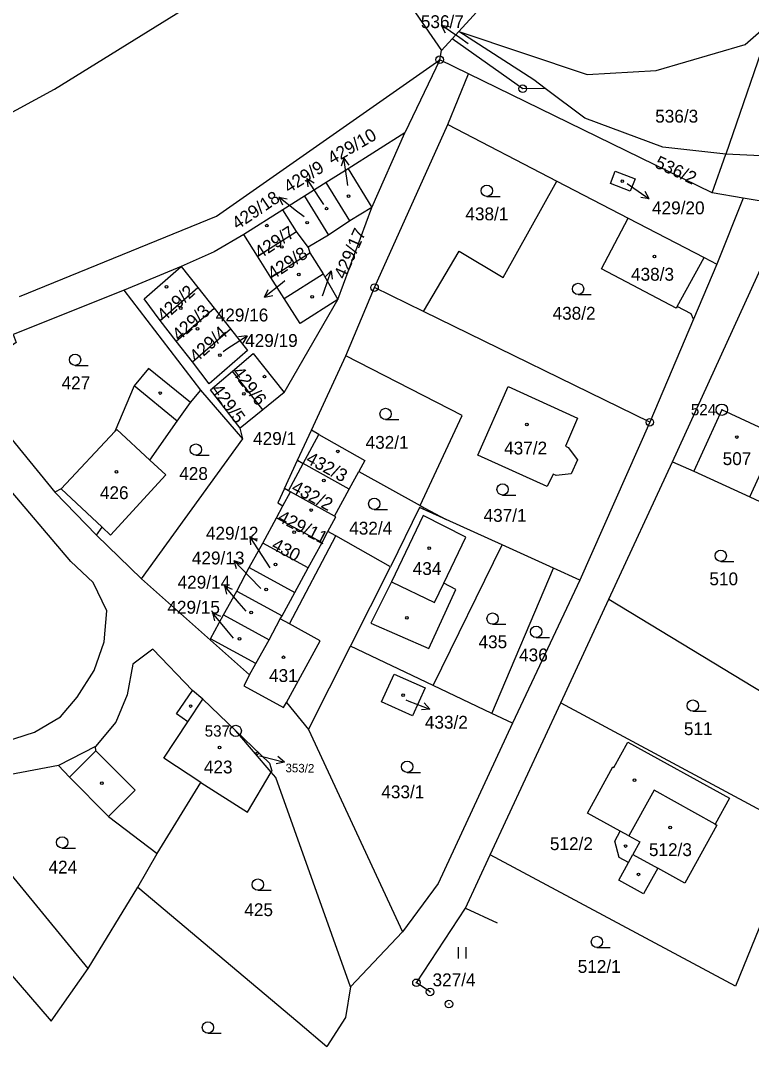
# Model space of a CAD drawing. Extents: x -776701 to -776081, y -974398 to -973771.
# Drawn here: x -776380.3 to -776283.6, y -974398.3 to -974262.5 of the extents above; entities that cross this region are included whole.
import ezdxf

# ---------------------------------------------------------------- set-up
doc = ezdxf.new("R2010")
doc.units = 0
for name, color, linetype in [('Hranice parcel', 7, 'Continuous'), ('Parcelní čísla', 7, 'Continuous'), ('Pop  PČ popisy', 7, 'Continuous'), ('Poz předměty', 7, 'Continuous'), ('Vnitřní kresba', 7, 'Continuous'), ('Značky bodu BP', 7, 'Continuous'), ('Značky budov', 7, 'Continuous'), ('Značky kultur', 7, 'Continuous')]:
    doc.layers.add(name, color=color, linetype=linetype)

msp = doc.modelspace()

# ---------------------------------------------------------------- linework, layer by layer
at = {"layer": 'Hranice parcel'}
for p, q in [((-776280.95, -974262.62), (-776287.02, -974280.17)), ((-776323.22, -974264.9), (-776322.34, -974263.94)), ((-776288.8, -974285.31), (-776287.02, -974280.17)), ((-776279.48, -974280.55), (-776287.02, -974280.17)), ((-776336.99, -974282.11), (-776339.88, -974283.93)), ((-776339.88, -974283.93), (-776342.75, -974285.75)), ((-776336.75, -974289), (-776339.88, -974283.93)), ((-776309.36, -974283.76), (-776299.93, -974288.65)), ((-776342.75, -974285.75), (-776345.62, -974287.57)), ((-776342.75, -974285.75), (-776339.6, -974290.9)), ((-776284.72, -974286.01), (-776288.8, -974285.31)), ((-776284.72, -974286.01), (-776288.19, -974294.73)), ((-776275.72, -974287.55), (-776284.72, -974286.01)), ((-776345.62, -974287.57), (-776350.78, -974290.83)), ((-776343.81, -974290.44), (-776345.62, -974287.57)), ((-776336.75, -974289), (-776339.6, -974290.9)), ((-776299.93, -974288.65), (-776289.9, -974293.84)), ((-776348.97, -974293.7), (-776343.81, -974290.44)), ((-776342.3, -974292.5), (-776343.81, -974290.44)), ((-776348.97, -974293.7), (-776350.78, -974290.83)), ((-776339.6, -974290.9), (-776342.3, -974292.5)), ((-776347.2, -974296.49), (-776342.04, -974293.23)), ((-776342.3, -974292.5), (-776342.04, -974293.23)), ((-776342.04, -974293.23), (-776340.28, -974296.02)), ((-776347.2, -974296.49), (-776348.97, -974293.7)), ((-776289.9, -974293.84), (-776288.19, -974294.73)), ((-776288.19, -974294.73), (-776291.28, -974302.01)), ((-776345.44, -974299.28), (-776347.2, -974296.49)), ((-776345.44, -974299.28), (-776340.28, -974296.02)), ((-776366.62, -974298.19), (-776381.33, -974304.06)), ((-776356.49, -974311.44), (-776366.62, -974298.19)), ((-776361.87, -974302.2), (-776356.9, -974297.82)), ((-776356.9, -974297.82), (-776354.73, -974300.57)), ((-776337.3, -974306.86), (-776333.5, -974297.85)), ((-776327.02, -974301.02), (-776333.5, -974297.85)), ((-776359.74, -974304.94), (-776354.73, -974300.57)), ((-776354.73, -974300.57), (-776352.57, -974303.31)), ((-776297.07, -974315.67), (-776327.02, -974301.02)), ((-776359.74, -974304.94), (-776361.87, -974302.2)), ((-776291.28, -974302.01), (-776297.07, -974315.67)), ((-776357.6, -974307.68), (-776352.57, -974303.31)), ((-776357.6, -974307.68), (-776359.74, -974304.94)), ((-776348.28, -974314.03), (-776352.31, -974308.92)), ((-776357.83, -974313.04), (-776356.49, -974311.44)), ((-776297.07, -974315.67), (-776306.32, -974336.58)), ((-776343.69, -974320.7), (-776342.94, -974321.12)), ((-776336.85, -974324.51), (-776342.94, -974321.12)), ((-776302.5, -974339.06), (-776294.07, -974320.91)), ((-776294.07, -974320.91), (-776291.26, -974322.16)), ((-776368.42, -974330.59), (-776361.1, -974322.64)), ((-776336.85, -974324.51), (-776335.58, -974322.18)), ((-776335.58, -974322.18), (-776327.45, -974326.69)), ((-776291.26, -974322.16), (-776283.82, -974325.55)), ((-776375.79, -974324.92), (-776370.28, -974330.61)), ((-776338.81, -974328.09), (-776344.62, -974324.87)), ((-776338.81, -974328.09), (-776336.85, -974324.51)), ((-776283.82, -974325.55), (-776270.54, -974331.71)), ((-776348.3, -974331.65), (-776346.48, -974328.3)), ((-776346.48, -974328.3), (-776340.45, -974331.57)), ((-776316.6, -974331.91), (-776324.04, -974328.54)), ((-776370.28, -974330.61), (-776364.35, -974336.4)), ((-776340.45, -974331.57), (-776339.66, -974330.11)), ((-776350.07, -974334.91), (-776348.3, -974331.65)), ((-776342.26, -974334.92), (-776348.3, -974331.65)), ((-776342.26, -974334.92), (-776340.45, -974331.57)), ((-776325.72, -974350.5), (-776316.6, -974331.91)), ((-776309.81, -974334.99), (-776316.6, -974331.91)), ((-776351.74, -974338), (-776350.07, -974334.91)), ((-776350.07, -974334.91), (-776344.03, -974338.19)), ((-776344.03, -974338.19), (-776342.26, -974334.92)), ((-776336.7, -974345.3), (-776331.37, -974334.81)), ((-776317.97, -974354.21), (-776309.81, -974334.99)), ((-776306.32, -974336.58), (-776309.81, -974334.99)), ((-776364.35, -974336.4), (-776350.04, -974349.11)), ((-776306.32, -974336.58), (-776315.26, -974355.5)), ((-776353.47, -974341.17), (-776351.74, -974338)), ((-776351.74, -974338), (-776345.71, -974341.27)), ((-776345.71, -974341.27), (-776344.03, -974338.19)), ((-776308.85, -974352.8), (-776302.5, -974339.06)), ((-776302.5, -974339.06), (-776278.24, -974353.79)), ((-776353.47, -974341.17), (-776347.43, -974344.44)), ((-776349.2, -974347.58), (-776347.43, -974344.44)), ((-776342.23, -974356.34), (-776336.7, -974345.3)), ((-776325.72, -974350.5), (-776336.7, -974345.3)), ((-776350.04, -974349.11), (-776349.2, -974347.58)), ((-776317.97, -974354.21), (-776325.72, -974350.5)), ((-776318.19, -974372.93), (-776308.85, -974352.8)), ((-776308.85, -974352.8), (-776277.4, -974369.72)), ((-776315.26, -974355.5), (-776317.97, -974354.21)), ((-776347.17, -974361.99), (-776351.87, -974356.52)), ((-776342.23, -974356.34), (-776329.79, -974383.11)), ((-776362.24, -974372.74), (-776356.48, -974363.36)), ((-776371.4, -974387.94), (-776390.84, -974364.25)), ((-776400.26, -974367.17), (-776376.3, -974394.94)), ((-776277.4, -974369.72), (-776285.72, -974390.31)), ((-776364.8, -974377.2), (-776362.24, -974372.74)), ((-776321.45, -974379.97), (-776318.19, -974372.93)), ((-776285.72, -974390.31), (-776318.19, -974372.93)), ((-776371.4, -974387.94), (-776364.8, -974377.2)), ((-776364.8, -974377.2), (-776343.63, -974395.04)), ((-776327.95, -974389.85), (-776321.45, -974379.97)), ((-776321.45, -974379.97), (-776317.26, -974381.91)), ((-776329.79, -974383.11), (-776336.7, -974390.37)), ((-776376.3, -974394.94), (-776371.4, -974387.94)), ((-776326.15, -974391.06), (-776327.95, -974389.85)), ((-776343.63, -974395.04), (-776339.79, -974398.28))]:
    msp.add_line(p, q, dxfattribs=at)
for points in [[(-776322.34, -974263.94), (-776316.64, -974257.67), (-776307.88, -974259.63), (-776300.82, -974259.07), (-776293.46, -974256.12), (-776281.91, -974242.23)], [(-776322.34, -974263.94), (-776305.38, -974269.65), (-776296.22, -974269.13), (-776284.45, -974265.69), (-776280.95, -974262.62)], [(-776310.94, -974271.48), (-776312.43, -974270.36), (-776322.34, -974263.94)], [(-776324.88, -974267.68), (-776324.63, -974266.46), (-776323.22, -974264.9)], [(-776310.94, -974271.48), (-776313.89, -974271.52), (-776323.22, -974264.9)], [(-776380.5, -974299.02), (-776354.39, -974288.37), (-776324.88, -974267.68)], [(-776324.88, -974267.68), (-776329.47, -974277.36), (-776336.99, -974282.11)], [(-776288.8, -974285.31), (-776321.08, -974269.54), (-776324.88, -974267.68)], [(-776287.02, -974280.17), (-776295.33, -974279.25), (-776305.65, -974275.44), (-776310.94, -974271.48)], [(-776333.5, -974297.85), (-776323.82, -974276.26), (-776309.36, -974283.76)], [(-776336.99, -974282.11), (-776333.86, -974287.23), (-776336.75, -974289)], [(-776301.64, -974282.42), (-776299, -974283.46), (-776299.66, -974285.07), (-776302.28, -974284.07), (-776301.64, -974282.42)], [(-776327.02, -974301.02), (-776322.3, -974293.03), (-776316.46, -974296.49), (-776309.36, -974283.76)], [(-776291.28, -974302.01), (-776291.59, -974301.3), (-776293.47, -974300.35), (-776293.59, -974300.57), (-776303.47, -974295.37), (-776299.93, -974288.65)], [(-776350.78, -974290.83), (-776354.72, -974293.13), (-776359.09, -974295.04), (-776366.62, -974298.19)], [(-776294.07, -974320.91), (-776281.24, -974292.8), (-776280.11, -974290.91)], [(-776361.87, -974302.2), (-776364, -974299.35), (-776359.09, -974295.04), (-776356.9, -974297.82)], [(-776340.28, -974296.02), (-776338.37, -974299.42), (-776343.35, -974302.58), (-776345.44, -974299.28)], [(-776381.33, -974304.06), (-776380.93, -974305.13), (-776384.89, -974307.87), (-776385.42, -974309.83), (-776385.09, -974312.64), (-776383.44, -974315.62), (-776375.79, -974324.92)], [(-776352.57, -974303.31), (-776350.3, -974306.18), (-776355.38, -974310.58), (-776357.6, -974307.68)], [(-776352.31, -974308.92), (-776349.57, -974306.58), (-776345.45, -974311.72), (-776348.28, -974314.03)], [(-776343.69, -974320.7), (-776341.86, -974316.73), (-776337.3, -974306.86)], [(-776327.45, -974326.69), (-776321.89, -974314.77), (-776337.3, -974306.86)], [(-776383.87, -974358.38), (-776378.5, -974356.68), (-776375.04, -974354.64), (-776372.83, -974352.03), (-776370.62, -974348.5), (-776369.27, -974344.71), (-776368.91, -974340.64), (-776370.74, -974336.88), (-776373.7, -974334.1), (-776391.97, -974312.58), (-776393.45, -974309.32)], [(-776357.83, -974313.04), (-776363.4, -974308.53), (-776365.3, -974310.86), (-776367.86, -974316.89), (-776374.96, -974324.46), (-776375.79, -974324.92)], [(-776348.28, -974314.03), (-776351.28, -974316.46), (-776355.2, -974311.38), (-776352.31, -974308.92)], [(-776364.35, -974336.4), (-776350.91, -974317.88), (-776356.49, -974311.44)], [(-776309.88, -974322.53), (-776310.64, -974324.19), (-776319.84, -974320.01), (-776315.83, -974310.94), (-776306.65, -974315.14), (-776308.25, -974318.84), (-776307.86, -974319.01), (-776306.66, -974320.63), (-776307.5, -974322.47), (-776309.47, -974322.71), (-776309.88, -974322.53)], [(-776361.1, -974322.64), (-776363.24, -974320.67), (-776359.6, -974315.52), (-776357.83, -974313.04)], [(-776283.82, -974325.55), (-776280.13, -974317.46), (-776287.54, -974314), (-776291.26, -974322.16)], [(-776342.94, -974321.12), (-776340.87, -974317.29), (-776334.78, -974320.71), (-776335.58, -974322.18)], [(-776344.62, -974324.87), (-776344.9, -974324.72), (-776345.42, -974324.44), (-776343.69, -974320.7)], [(-776346.48, -974328.3), (-776345.63, -974326.73), (-776344.62, -974324.87)], [(-776324.04, -974328.54), (-776327.56, -974326.94), (-776331.37, -974334.81)], [(-776327.45, -974326.69), (-776326.94, -974326.97), (-776324.04, -974328.54)], [(-776339.66, -974330.11), (-776338.61, -974328.2), (-776338.81, -974328.09)], [(-776370.28, -974330.61), (-776369.53, -974329.55), (-776368.42, -974330.59)], [(-776331.37, -974334.81), (-776338.64, -974330.69), (-776339.66, -974330.11)], [(-776349.2, -974347.58), (-776355.19, -974344.34), (-776353.47, -974341.17)], [(-776347.43, -974344.44), (-776345.98, -974341.7), (-776345.71, -974341.27)], [(-776351.87, -974356.52), (-776356.2, -974352.3), (-776357.6, -974351.15), (-776362.85, -974345.69), (-776365.48, -974347.69), (-776366.22, -974351.74), (-776367.74, -974355.38), (-776370.41, -974358.58), (-776375.3, -974361.1)], [(-776350.04, -974349.11), (-776350.79, -974350.53), (-776345.53, -974353.4), (-776345.17, -974352.74), (-776342.23, -974356.34)], [(-776326.82, -974350.83), (-776328.48, -974354.52), (-776332.58, -974352.68), (-776330.92, -974348.99), (-776326.82, -974350.83)], [(-776315.26, -974355.5), (-776325.06, -974376.72), (-776329.79, -974383.11)], [(-776351.87, -974356.52), (-776347.38, -974360.77), (-776347.07, -974361.81), (-776347.17, -974361.99)], [(-776296.02, -974374.69), (-776297.89, -974378.09), (-776301.18, -974376.28), (-776299.9, -974373.95), (-776301.11, -974373.29), (-776301.72, -974371.1), (-776300.99, -974369.78), (-776305.33, -974367.39), (-776301.97, -974361.28), (-776301.82, -974361.36), (-776299.98, -974358.02), (-776286.51, -974365.42), (-776288.41, -974368.87)], [(-776375.3, -974361.1), (-776385.85, -974363.08), (-776390.84, -974364.25)], [(-776375.3, -974361.1), (-776373.87, -974362.65), (-776368.69, -974367.84), (-776362.24, -974372.74)], [(-776356.48, -974363.36), (-776350.29, -974367.25), (-776347.17, -974361.99)], [(-776336.7, -974390.37), (-776346.56, -974362.7), (-776347.17, -974361.99)], [(-776288.41, -974368.87), (-776288.19, -974368.99), (-776292.46, -974376.67), (-776296.02, -974374.69)], [(-776336.7, -974390.37), (-776337.32, -974394.45), (-776339.79, -974398.28)]]:
    msp.add_lwpolyline(points, dxfattribs=at)
at = {"layer": 'Pop  PČ popisy'}
for p, q in [((-776322.21, -974264.81), (-776324.7, -974263.13)), ((-776324.7, -974263.13), (-776323.59, -974263.28)), ((-776324.7, -974263.13), (-776324.15, -974264.11)), ((-776321.11, -974265.57), (-776322.21, -974264.81)), ((-776337.55, -974280.7), (-776337.9, -974281.76)), ((-776337.13, -974283.67), (-776337.55, -974280.7)), ((-776337.55, -974280.7), (-776336.91, -974281.62)), ((-776340.81, -974285.91), (-776342.44, -974283.39)), ((-776342.44, -974283.39), (-776341.48, -974283.96)), ((-776342.44, -974283.39), (-776342.32, -974284.51)), ((-776337.04, -974284.31), (-776337.13, -974283.67)), ((-776300.06, -974284.08), (-776299.63, -974284.37)), ((-776299.63, -974284.37), (-776297.17, -974286.09)), ((-776297.17, -974286.09), (-776297.7, -974285.11)), ((-776343.81, -974287.72), (-776346.18, -974285.87)), ((-776346.18, -974285.87), (-776345.08, -974286.09)), ((-776346.18, -974285.87), (-776345.69, -974286.88)), ((-776340.19, -974286.86), (-776340.81, -974285.91)), ((-776297.17, -974286.09), (-776298.28, -974285.93)), ((-776342.82, -974288.48), (-776343.81, -974287.72)), ((-776340.21, -974298.47), (-776339.23, -974295.63)), ((-776339.23, -974295.63), (-776340.03, -974296.42)), ((-776339.23, -974295.63), (-776339.09, -974296.74)), ((-776345.71, -974297.24), (-776348.04, -974299.13)), ((-776345.35, -974296.95), (-776345.71, -974297.24)), ((-776348.04, -974299.13), (-776347.58, -974298.11)), ((-776340.37, -974298.93), (-776340.21, -974298.47)), ((-776348.04, -974299.13), (-776346.95, -974298.89)), ((-776352.89, -974305.87), (-776350.37, -974304.24)), ((-776350.37, -974304.24), (-776351.49, -974304.36)), ((-776350.37, -974304.24), (-776350.94, -974305.2)), ((-776353.54, -974306.3), (-776352.89, -974305.87)), ((-776348.38, -974333.29), (-776350.01, -974330.77)), ((-776350.01, -974330.77), (-776349.05, -974331.34)), ((-776350.01, -974330.77), (-776349.89, -974331.89)), ((-776350.04, -974336.11), (-776352.12, -974333.95)), ((-776352.12, -974333.95), (-776351.07, -974334.32)), ((-776352.12, -974333.95), (-776351.79, -974335.02)), ((-776347.32, -974334.95), (-776348.38, -974333.29)), ((-776348.53, -974337.67), (-776350.04, -974336.11)), ((-776351.39, -974339.6), (-776353.36, -974337.33)), ((-776353.36, -974337.33), (-776352.32, -974337.76)), ((-776353.36, -974337.33), (-776353.08, -974338.42)), ((-776350.47, -974340.65), (-776351.39, -974339.6)), ((-776353.03, -974343.2), (-776354.92, -974340.87)), ((-776354.92, -974340.87), (-776353.9, -974341.33)), ((-776354.92, -974340.87), (-776354.68, -974341.96)), ((-776352.18, -974344.25), (-776353.03, -974343.2)), ((-776329.35, -974352.41), (-776328.97, -974352.56)), ((-776328.97, -974352.56), (-776326.17, -974353.64)), ((-776326.17, -974353.64), (-776326.92, -974352.81)), ((-776326.17, -974353.64), (-776327.28, -974353.74)), ((-776348.73, -974359.8), (-776348.34, -974359.9)), ((-776348.34, -974359.9), (-776345.43, -974360.63)), ((-776345.43, -974360.63), (-776346.52, -974360.87)), ((-776345.43, -974360.63), (-776346.28, -974359.9))]:
    msp.add_line(p, q, dxfattribs=at)
at = {"layer": 'Poz předměty'}
for p, q in [((-776375.83, -974271.58), (-776358.8, -974261.05)), ((-776402.2, -974285.89), (-776375.83, -974271.58))]:
    msp.add_line(p, q, dxfattribs=at)
at = {"layer": 'Vnitřní kresba'}
for p, q in [((-776328.07, -974261.46), (-776324.63, -974266.46)), ((-776323.82, -974276.26), (-776321.08, -974269.54)), ((-776333.86, -974287.23), (-776329.47, -974277.36)), ((-776338.37, -974299.42), (-776333.86, -974287.23)), ((-776293.47, -974300.35), (-776289.9, -974293.84)), ((-776345.45, -974311.72), (-776338.37, -974299.42)), ((-776359.6, -974315.52), (-776365.3, -974310.86)), ((-776367.86, -974316.89), (-776367.62, -974316.64)), ((-776367.62, -974316.64), (-776363.24, -974320.67)), ((-776350.91, -974317.88), (-776351.28, -974316.46)), ((-776340.87, -974317.29), (-776341.86, -974316.73)), ((-776344.9, -974324.72), (-776342.94, -974321.12)), ((-776374.96, -974324.46), (-776369.53, -974329.55)), ((-776345.42, -974324.44), (-776346.3, -974326.35)), ((-776346.3, -974326.35), (-776345.63, -974326.73)), ((-776327.05, -974328), (-776331.25, -974336.8)), ((-776321.4, -974330.87), (-776327.05, -974328)), ((-776344.76, -974342.36), (-776338.64, -974330.69)), ((-776324.32, -974336.96), (-776321.4, -974330.87)), ((-776331.25, -974336.8), (-776334, -974342.27)), ((-776331.25, -974336.8), (-776325.56, -974339.53)), ((-776326.33, -974345.62), (-776322.73, -974337.79)), ((-776325.56, -974339.53), (-776324.32, -974336.96)), ((-776322.73, -974337.79), (-776324.32, -974336.96)), ((-776344.76, -974342.36), (-776345.98, -974341.7)), ((-776340.68, -974344.59), (-776344.76, -974342.36)), ((-776334, -974342.27), (-776326.33, -974345.62)), ((-776345.17, -974352.74), (-776340.68, -974344.59)), ((-776359.7, -974354.25), (-776357.6, -974351.15)), ((-776358.2, -974355.3), (-776356.2, -974352.3)), ((-776358.2, -974355.3), (-776359.7, -974354.25)), ((-776361.37, -974360.14), (-776358.2, -974355.3)), ((-776370.37, -974359.15), (-776373.87, -974362.65)), ((-776370.37, -974359.15), (-776370.41, -974358.58)), ((-776365.19, -974364.34), (-776370.37, -974359.15)), ((-776356.48, -974363.36), (-776361.37, -974360.14)), ((-776368.69, -974367.84), (-776365.19, -974364.34)), ((-776296.51, -974364.36), (-776299.86, -974370.4)), ((-776288.41, -974368.87), (-776296.51, -974364.36)), ((-776299.86, -974370.4), (-776300.99, -974369.78)), ((-776299.86, -974370.4), (-776298.39, -974371.21)), ((-776298.39, -974371.21), (-776299.3, -974372.87)), ((-776299.9, -974373.95), (-776299.3, -974372.87)), ((-776299.3, -974372.87), (-776296.02, -974374.69))]:
    msp.add_line(p, q, dxfattribs=at)
at = {"layer": 'Značky bodu BP'}
for centre, radius in [((-776324.88, -974267.68), 0.5), ((-776324.88, -974267.68), 0.0303), ((-776313.89, -974271.52), 0.5), ((-776313.89, -974271.52), 0.0303), ((-776333.5, -974297.85), 0.5), ((-776333.5, -974297.85), 0.0303), ((-776287.54, -974314), 0.75), ((-776287.54, -974314), 0.03), ((-776297.07, -974315.67), 0.5), ((-776297.07, -974315.67), 0.0303), ((-776351.87, -974356.52), 0.75), ((-776351.87, -974356.52), 0.03), ((-776327.95, -974389.85), 0.5), ((-776327.95, -974389.85), 0.0303), ((-776326.15, -974391.06), 0.5), ((-776326.15, -974391.06), 0.0303), ((-776323.66, -974392.66), 0.5), ((-776323.66, -974392.66), 0.0303)]:
    msp.add_circle(centre, radius, dxfattribs=at)
at = {"layer": 'Značky budov'}
for centre in [(-776300.71, -974283.76), (-776336.93, -974285.73), (-776339.84, -974287.39), (-776342.4, -974289.25), (-776347.74, -974289.64), (-776345.77, -974292.47), (-776296.47, -974293.74), (-776343.53, -974296.1), (-776361.04, -974297.74), (-776341.76, -974299.07), (-776359.15, -974300.56), (-776356.93, -974303.3), (-776353.95, -974306.8), (-776348.05, -974309.63), (-776361.85, -974311.8), (-776350.78, -974311.91), (-776313.33, -974315.96), (-776285.57, -974317.62), (-776338.36, -974319.52), (-776367.66, -974322.22), (-776340.2, -974323.38), (-776341.89, -974327.28), (-776344.13, -974330.22), (-776326.25, -974332.33), (-776346.6, -974334.49), (-776347.84, -974337.8), (-776349.81, -974340.84), (-776329.21, -974341.55), (-776351.36, -974344.32), (-776345.54, -974346.77), (-776329.73, -974351.79), (-776357.83, -974353.22), (-776354, -974358.71), (-776349.03, -974359.49), (-776369.58, -974363.42), (-776299.11, -974363.04), (-776294.37, -974369.29), (-776300.27, -974371.75), (-776298.56, -974375.5)]:
    msp.add_circle(centre, 0.175, dxfattribs=at)
at = {"layer": 'Značky kultur'}
for p, q in [((-776318.64, -974285.78), (-776316.89, -974285.78)), ((-776306.57, -974298.77), (-776304.82, -974298.77)), ((-776373.13, -974308.14), (-776371.38, -974308.14)), ((-776332.03, -974315.32), (-776330.28, -974315.32)), ((-776357.14, -974320.03), (-776355.39, -974320.03)), ((-776316.55, -974325.3), (-776314.8, -974325.3)), ((-776333.54, -974327.21), (-776331.79, -974327.21)), ((-776287.69, -974334.08), (-776285.94, -974334.08)), ((-776317.88, -974342.41), (-776316.13, -974342.41)), ((-776312.11, -974344.15), (-776310.36, -974344.15)), ((-776291.38, -974353.91), (-776289.63, -974353.91)), ((-776329.18, -974362), (-776327.43, -974362)), ((-776374.83, -974372.02), (-776373.08, -974372.02)), ((-776348.94, -974377.6), (-776347.19, -974377.6)), ((-776322.39, -974386.62), (-776322.39, -974385.12)), ((-776321.39, -974386.62), (-776321.39, -974385.12)), ((-776304.07, -974385.2), (-776302.32, -974385.2)), ((-776355.54, -974396.52), (-776353.79, -974396.52))]:
    msp.add_line(p, q, dxfattribs=at)
for centre in [(-776318.64, -974285.03), (-776306.57, -974298.02), (-776373.13, -974307.39), (-776332.03, -974314.57), (-776357.14, -974319.28), (-776316.55, -974324.55), (-776333.54, -974326.46), (-776287.69, -974333.33), (-776317.88, -974341.66), (-776312.11, -974343.4), (-776291.38, -974353.16), (-776329.18, -974361.25), (-776374.83, -974371.27), (-776348.94, -974376.85), (-776304.07, -974384.45), (-776355.54, -974395.77)]:
    msp.add_circle(centre, 0.75, dxfattribs=at)

# ---------------------------------------------------------------- texts
at = {"layer": 'Parcelní čísla'}
for s, p in [('536/7', (-776327.37, -974263.5)), ('536/3', (-776296.36, -974276.01)), ('429/20', (-776296.78, -974288.14)), ('438/1', (-776321.48, -974288.94)), ('438/3', (-776299.56, -974296.93)), ('429/16', (-776354.51, -974302.32)), ('438/2', (-776309.94, -974302.09)), ('429/19', (-776350.62, -974305.7)), ('427', (-776374.91, -974311.3)), ('429/1', (-776349.57, -974318.67)), ('432/1', (-776334.68, -974319.18)), ('437/2', (-776316.35, -974319.93)), ('507', (-776287.43, -974321.33)), ('428', (-776359.34, -974323.3)), ('426', (-776369.84, -974325.84)), ('437/1', (-776319.07, -974328.84)), ('429/12', (-776355.81, -974331.2)), ('432/4', (-776336.85, -974330.53)), ('429/13', (-776357.67, -974334.48)), ('434', (-776328.45, -974335.88)), ('429/14', (-776359.56, -974337.69)), ('510', (-776289.19, -974337.24)), ('429/15', (-776360.91, -974341)), ('435', (-776319.74, -974345.57)), ('436', (-776314.37, -974347.31)), ('431', (-776347.46, -974350.04)), ('433/2', (-776326.84, -974356.22)), ('511', (-776292.56, -974357.07)), ('423', (-776356.08, -974362.14)), ('433/1', (-776332.6, -974365.43)), ('512/2', (-776310.29, -974372.29)), ('512/3', (-776297.19, -974373.08)), ('424', (-776376.64, -974375.39)), ('425', (-776350.73, -974381.03)), ('512/1', (-776306.61, -974388.54)), ('327/4', (-776325.82, -974390.31))]:
    msp.add_text(s, height=1.7, dxfattribs=at).set_placement(p)
for s, height, rotation, p in [('429/10', 1.7, 30, (-776339.09, -974281.61)), ('536/2', 1.7, 335, (-776296.55, -974281.86)), ('429/9', 1.7, 32, (-776344.84, -974285.4)), ('429/18', 1.7, 34, (-776351.64, -974290.24)), ('429/7', 1.7, 33, (-776348.67, -974294.1)), ('429/17', 1.7, 66, (-776337.41, -974296.84)), ('429/8', 1.7, 33, (-776346.95, -974296.85)), ('429/2', 1.7, 42, (-776361.35, -974302.42)), ('429/3', 1.7, 42, (-776359.35, -974304.99)), ('429/4', 1.7, 42, (-776357.06, -974307.86)), ('429/6', 1.7, 307, (-776352.42, -974309.07)), ('429/5', 1.7, 306, (-776355.19, -974311.36)), ('432/3', 1.7, 332, (-776342.7, -974320.98)), ('432/2', 1.7, 332, (-776344.63, -974324.78)), ('429/11', 1.7, 333, (-776346.45, -974328.72)), ('430', 1.7, 332, (-776347.25, -974332.39)), ('353/2', 1.139, 359, (-776345.29, -974361.98))]:
    msp.add_text(s, height=height, rotation=rotation, dxfattribs=at).set_placement(p)
at = {"layer": 'Značky bodu BP'}
for s, p in [('524', (-776291.64, -974314.75)), ('537', (-776355.97, -974357.27))]:
    msp.add_text(s, height=1.5, dxfattribs=at).set_placement(p)

doc.saveas('drawing.dxf')
